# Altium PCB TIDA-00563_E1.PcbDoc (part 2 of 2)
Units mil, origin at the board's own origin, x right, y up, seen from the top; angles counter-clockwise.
Board outline 2300 x 2550 mil, 4 copper layers (Top Layer, MidLayer1 (GND), MidLayer2 (PWR), Bottom Layer), stack 79.8 mil thick; 81 components, 52 nets, 279 pads, 126 vias.
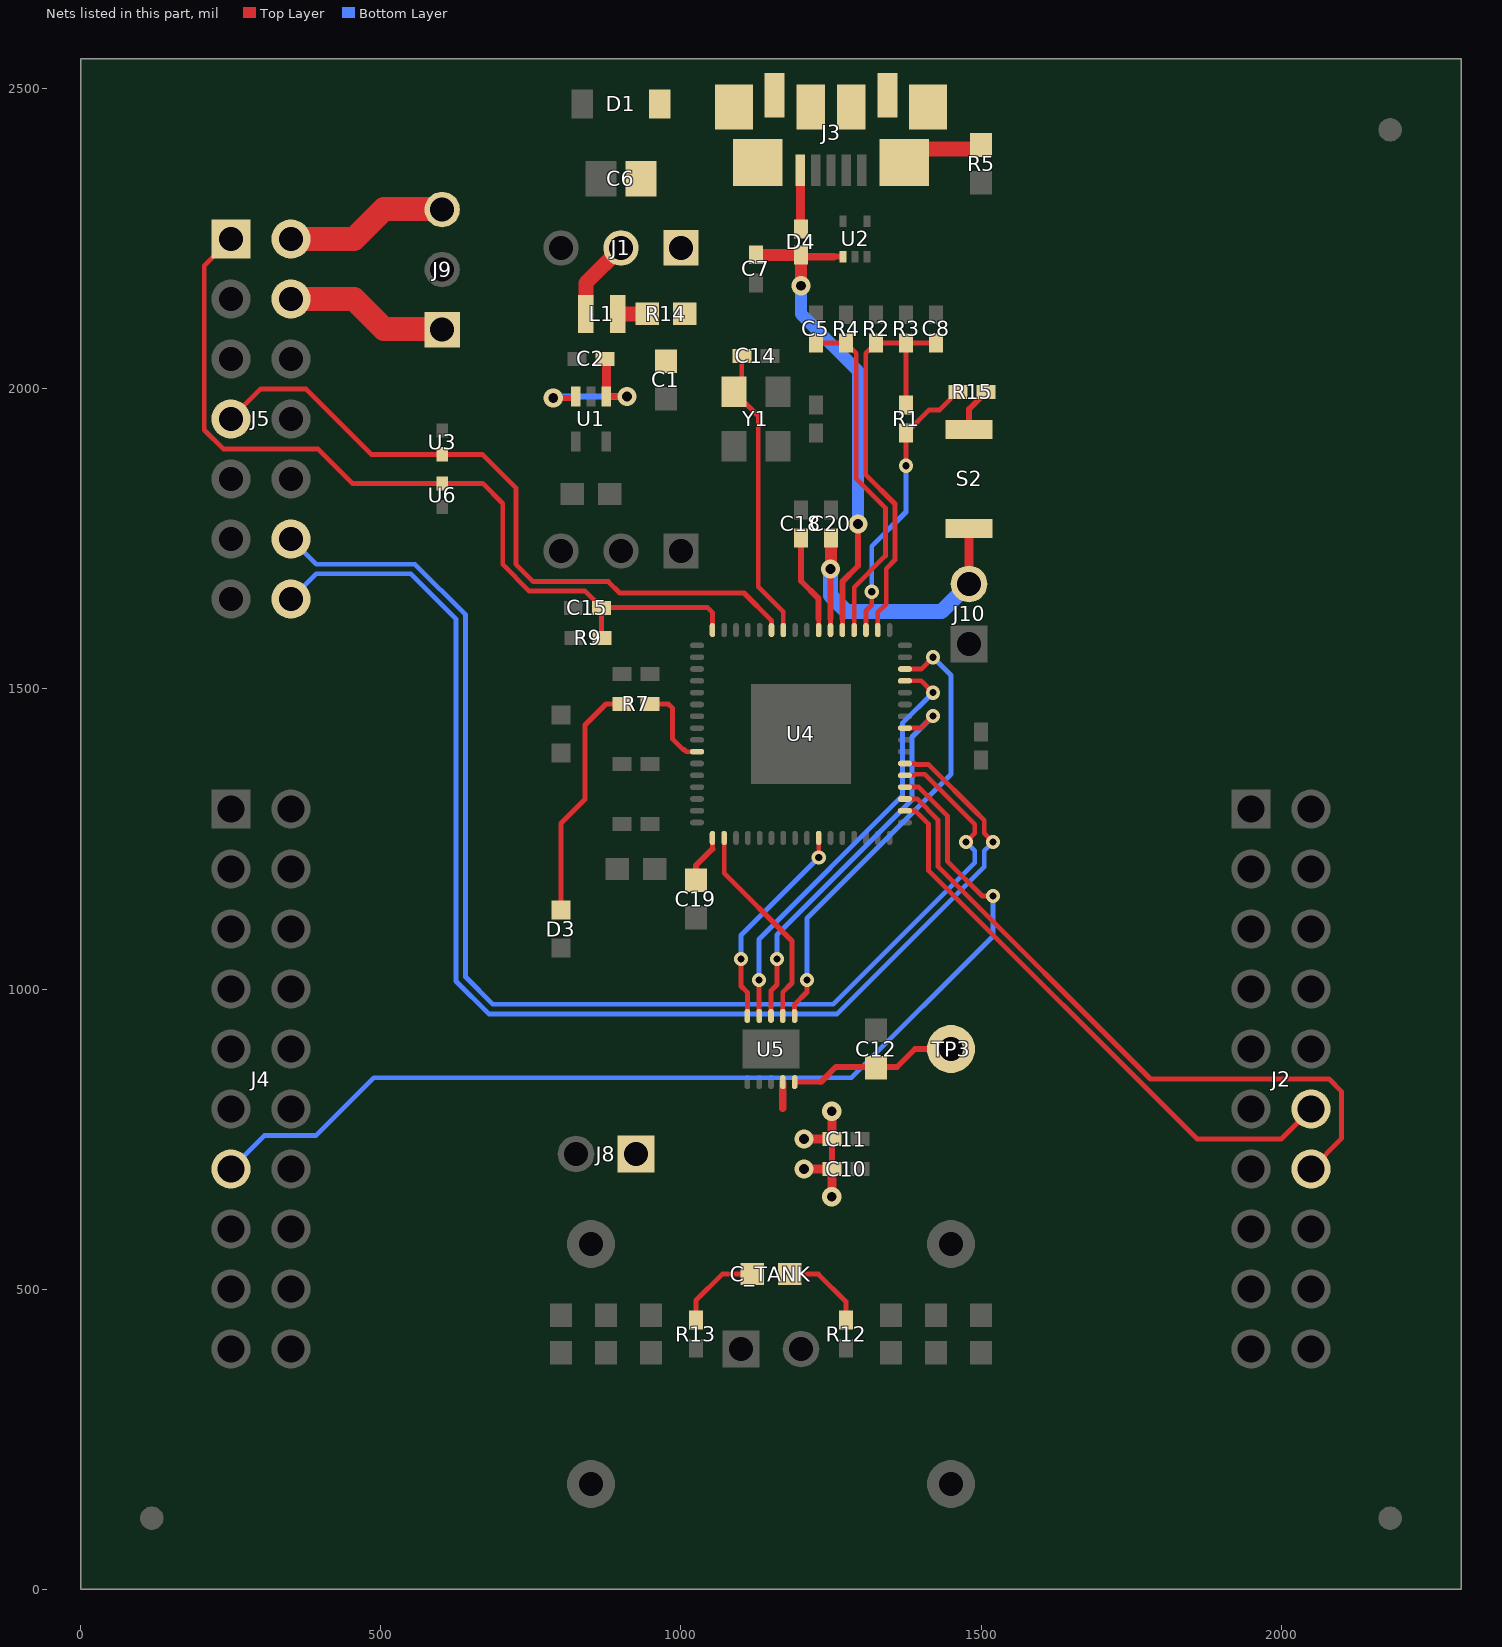
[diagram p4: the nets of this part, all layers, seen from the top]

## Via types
v1: diameter 32, hole 16, Top Layer to Bottom Layer, tented both sides, 96 vias
v2: diameter 19.68, hole 7.87, Top Layer to Bottom Layer, 17 vias
v3: diameter 24, hole 12, Top Layer to Bottom Layer, tented both sides, 13 vias

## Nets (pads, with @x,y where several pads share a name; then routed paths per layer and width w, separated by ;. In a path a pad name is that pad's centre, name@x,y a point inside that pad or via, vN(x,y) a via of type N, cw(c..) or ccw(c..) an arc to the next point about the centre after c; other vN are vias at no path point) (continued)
LDO_IN: C1.1 C2.1 R14.2 U1.1 U1.3 | length 258.5
  Top Layer w10: v1(787,1985) 822.01,1985 U1.3@824.41,1987.4 ; U1.1@875.59,1985 877.99,1987.4 v1(910.04,1987.4)
  Top Layer w15: U1.1@875.59,1987.4 C2.1@875.59,2048.03
  Bottom Layer w10: v1(787,1985) 789.4,1987.4 v1(910.04,1987.4)
MCU_CLKIN: U4.18 U5.2 | length 349.8
  Top Layer w8: U4.18@1072.02,1251.77 1072.02,1192.98 1185,1080 1185,1010 1169.69,994.69 U5.2@1169.69,955.11
MCU_CSB: U4.26 U5.5 | length 354.7
  Top Layer w8: v3(1100,1050) 1100,1005 1110.63,994.37 U5.5@1110.63,955.11 ; v3(1229.54,1219.2) U4.26@1229.54,1251.77
  Bottom Layer w8: v3(1100,1050) 1100,1089.66 v3(1229.54,1219.2)
MCU_SCLK: U4.41 U5.3 | length 666.8
  Top Layer w8: U5.3@1150,955.11 1150,997.45 1160,1007.45 v3(1160,1050) ; U4.41@1373.23,1434.84 1399.84,1434.84 v3(1420,1455)
  Bottom Layer w8: v3(1160,1050) 1160,1090.45 1385,1315.45 1385,1420 v3(1420,1455)
MCU_SDI: U4.45 U5.4 | length 714.1
  Top Layer w8: v3(1130,1015) 1130,955.43 U5.4@1130.32,955.11 ; U4.45@1373.23,1513.58 1400.26,1513.58 v3@1420,1493.84
  Bottom Layer w8: v3(1130,1015) 1130,1082.9 1369.13,1322.02 1369.13,1443.13 v3(1420,1494)
MISO_BP: J2.14 U4.35 | length 1125.4
  Top Layer w8: U4.35@1373.23,1316.73 1393.37,1316.73 1428.13,1281.98 1428.13,1204.32 1782.45,850 2080,850 2101,829 2101,751 J2.14@2050,700
MOSI_BP: J2.12 U4.34 | length 969.6
  Top Layer w8: U4.34@1373.23,1297.04 1390.61,1297.04 1412.25,1275.4 1412.25,1197.75 1860,750 2000,750 J2.12@2050,800
MSP_DM: C5.1 R4.2 U4.52 | length 576.9
  Top Layer w8: C5.1@1225,2076.38 R4.2@1275,2076.37 1292,2059.37 1292,1850.37 1340.69,1801.69 1340.69,1721.69 1288.61,1669.61 U4.52@1288.61,1598.23
MSP_DP: C8.1 R1.1 R2.2 R3.2 U4.50 | length 721.2
  Top Layer w8: U4.50@1327.99,1598.23 1327.99,1627.54 1342,1641.55 1342,1700.37 1356.69,1715.06 1356.69,1808.31 1308,1857 1308,2059.37 R2.2@1325,2076.37 R3.2@1375,2076.37 ; R1.1@1375,1973.62 R3.2@1375,2076.37 ; R3.2@1375.87,2075.5 R3.2@1375,2076.37 ; C8.1@1425,2076.38 R3.2@1375,2076.37
MSP_PUR: R1.2 R15.1 U4.51 | length 470.6
  Top Layer w8: U4.51@1308.3,1598.23 1308.3,1630.3 1318,1640 v3(1318,1662) ; v3(1375,1872) R1.2@1375,1926.38 1413.62,1965 1431.38,1965 R15.1@1461.38,1995
  Bottom Layer w8: v3(1318,1662) 1318,1738 1375,1795 v3(1375,1872)
MSP_XT2: C14.1 U4.58 Y1.3 | length 496
  Top Layer w8: C14.1@1101.38,2055 1101.38,2008.07 Y1.3@1088.59,1995.27 1128.88,1954.98 1128.88,1670.67 1170.47,1629.08 U4.58@1170.47,1598.23
MSPV18: C18.1 U4.55 | length 165.4
  Top Layer w8: U4.55@1229.54,1598.23 1229.54,1617
  Top Layer w10: C18.1@1200,1751.38 1200,1680 1229.54,1650.46 1229.54,1617
MSPVCORE: C19.1 U4.17 | length 81.6
  Top Layer w8: 1052.33,1233.33 U4.17@1052.33,1251.77
  Top Layer w10: C19.1@1025,1181.49 1025,1206 1052.33,1233.33
NetC10_1: C10.1 C11.1 J8.1 U5.9 | length 279.1
  Top Layer w10: C10.1@1251.38,700 C11.1@1251.38,750
  Top Layer w12: 1169.69,801.31 U5.9@1169.69,844.88
  Top Layer w15: v1(1205,700) C10.1@1251.38,700 v1(1251.38,653.62) ; v1(1205,750) C11.1@1251.38,750 v1(1251.38,796.38)
NetC12_1: C12.1 TP3.1 U5.10 | length 285.6
  Top Layer w8: U5.10@1189.37,844.88 1232.88,844.88 ; C12.1@1323.51,870 C12.1@1325,868.5
  Top Layer w10: 1232.88,844.88 1258,870 1323.51,870 1360,870 1390,900 TP3.1@1450,900
NetC_TANK_1: C_TANK.1 R12.1 | length 142.9
  Top Layer w8: C_TANK.1@1181.5,525 1229,525 1275,479 R12.1@1275,448.62
NetC_TANK_2: C_TANK.2 R13.2 | length 144.1
  Top Layer w8: R13.2@1025,448.62 1025,481 1069,525 C_TANK.2@1118.5,525
NetD4_2: D4.2 J3.1 | length 91.7
  Top Layer w15: D4.2@1198.82,2272.83 J3.1@1198.82,2364.49
NetJ1_2: J1.2 L1.1 | length 134.3
  Top Layer w25: L1.1@841.43,2125 841.43,2176.43 J1.2@900,2235
NetL1_2: L1.2 R14.1 | length 48.9
  Top Layer w25: L1.2@894.57,2125 R14.1@943.5,2125
NetR15_2: R15.2 S2.1 | length 74.2
  Top Layer w10: S2.1@1480,1932.68 1480,1966.38 R15.2@1508.62,1995
RLED: R7.1 U4.10 | length 141.3
  Top Layer w8: R7.1@948.63,1475 979.13,1475 986,1468.13 986,1416.55 1003.27,1399.28 1005.28,1399.28 1009.09,1395.47 U4.10@1026.78,1395.47
RLEDA: D3.2 R7.2 | length 401
  Top Layer w8: D3.2@800,1131.5 800,1276 840,1316 840,1440 875,1475 R7.2@901.38,1475
SBWTCK: J5.7 U3.1 U4.59 | length 1184.7
  Top Layer w8: J5.7@250,1950 300,2000 374.86,2000 483.86,1891 669,1891 ; 656,1891 669,1891 ; U4.59@1150.78,1598.23 1150.78,1614.22 1105,1660 898,1660 879,1679 754,1679 725,1708 725,1835 669,1891
SBWTDIO: C15.1 J5.1 R9.2 U4.64 U6.1 | length 1449.6
  Top Layer w8: J5.1@250,2250 205.65,2205.65 205.65,1931.63 237.27,1900 395,1900 452.32,1842.68 U6.1@602,1842.68 669.32,1842.68 702.87,1809.13 702.87,1707.68 747.42,1663.13 840.5,1663.13 C15.1@867.62,1636 ; R9.2@868.63,1585 867.62,1586 C15.1@867.62,1635 C15.1@867.62,1636 ; U4.64@1052.33,1598.23 1052.33,1627.67 1044,1636 C15.1@867.62,1636
SCLK_BP: J4.13 U4.36 | length 1763.9
  Top Layer w8: U4.36@1373.23,1336.41 1396.14,1336.41 1444,1288.55 1444,1213 1502,1155 v3(1520,1155)
  Bottom Layer w8: J4.13@250,700 305.65,755.65 391.65,755.65 488,852 1284,852 1520,1088 v3(1520,1155)
SDO: U4.46 U5.1 | length 773.2
  Top Layer w8: U5.1@1189.37,955.11 1189.37,974.37 1210,995 v3(1210,1015) ; U4.46@1373.23,1533.26 1400.26,1533.26 v3(1420,1553)
  Bottom Layer w8: v3(1210,1015) 1210,1118 1450,1358 1450,1523 v3(1420,1553)
UART_RXD: J5.14 U4.38 | length 2192.7
  Top Layer w8: U4.38@1373.23,1375.78 1389.04,1375.78 1390.89,1373.94 1412.69,1373.94 1495.81,1290.81 ; 1496,1290.63 1505.5,1281.13 1505.5,1259.5 v3(1520,1245)
  Bottom Layer w8: J5.14@350,1650 392,1692 550,1692 625,1617 625,1013.37 679.87,958.5 1260.5,958.5 1505.5,1203.5 1505.5,1230.5 v3(1520,1245)
UART_TXD: J5.12 U4.37 | length 2139.9
  Top Layer w8: U4.37@1373.23,1356.1 1389.04,1356.1 1390.89,1357.94 1406.06,1357.94 1489.5,1274.5 1489.5,1259.5 v3(1475,1245)
  Bottom Layer w8: J5.12@350,1750 392,1708 556.63,1708 641,1623.63 641,1020 686.5,974.5 1253.87,974.5 1489.5,1210.13 1489.5,1230.5 v3(1475,1245)
UGND: J3.6 J3.7 J3.8 J3.9 J3.10 J3.11 J3.12 J3.13 R5.2 | length 140
  Top Layer w20: J3.6@1372.05,2377.48 J3.6@1394.57,2400
  Top Layer w25: J3.6@1394.57,2400 1493.5,2400 R5.2@1500,2406.5
VBUS: C6.1 C7.1 D1.1 D4.1 J1.1 U2.1 U4.53 | length 821.9
  Top Layer w8: U4.53@1268.92,1598.23 1268.92,1616 1268.92,1617
  Top Layer w10: D4.1@1200,2223.35 D4.1@1202.87,2220.47 ; 1255,2220.47 U2.1@1270.31,2220.47 ; 1268.92,1617 1268.92,1678.86 1295,1704.94 v1(1295,1775)
  Top Layer w12: D4.1@1202.87,2220.47 1255,2220.47
  Top Layer w15: C7.1@1125,2223.62 C7.1@1125.28,2223.35
  Top Layer w20: C7.1@1125.28,2223.35 D4.1@1200,2223.35 v1(1200,2171.97)
  Bottom Layer w20: v1(1200,2171.97) 1200,2125 1295,2030 v1(1295,1775)
VCC_TARGET: J5.4 J9.1 | length 287.7
  Top Layer w10: J9.1@602,2083 J9.1@602,2099
  Top Layer w40: J5.4@350,2150 455,2150 505,2100 J9.1@601,2100
VCC_TOOL: J5.2 J9.3 | length 289.1
  Top Layer w10: J9.3@586,2283 J9.3@602,2283
  Top Layer w40: J5.2@350,2250 455,2250 505,2300 601,2300 J9.3@602,2299
VUSB: C20.1 J10.2 S2.2 U4.54 | length 550.9
  Top Layer w8: U4.54@1249.23,1598.23 1249.23,1617
  Top Layer w10: 1249.23,1617 v1(1249.23,1700)
  Top Layer w15: J10.2@1480,1675 S2.2@1480,1767.32
  Top Layer w20: v1(1249.23,1700) 1250,1700.77 C20.1@1250,1751.38
  Bottom Layer w25: v1(1249.23,1700) 1249.23,1655.77 1276,1629 1434,1629 J10.2@1480,1675
pads on no net: FID1.1 FID2.1 FID3.1 J2.1 J2.3 J2.4 J2.5 J2.6 J2.7 J2.8 J2.9 J2.10 J2.11 J2.13 J2.16 J2.20 J3.4 J4.3 J4.5 J4.6 J4.7 J4.8 J4.9 J4.10 J4.11 J4.12 J4.14 J4.15 J4.16 J4.17 J4.18 J4.19 J4.20 J5.3 J5.5 J5.6 J5.8 J5.10 J5.11 J5.13 SH-J1.0 SH-J7.0 SH-J8.0 SH-J9.0 SH-J10.0 U1.4 U4.1 U4.2 U4.3 U4.4 U4.5 U4.6 U4.7 U4.8 U4.12 U4.13 U4.19 U4.20 U4.21 U4.22 U4.23 U4.24 U4.25 U4.27 U4.28 U4.29 U4.42 U4.43 U4.44 U4.47 U4.48 U4.60 U4.61 U4.62 U4.63

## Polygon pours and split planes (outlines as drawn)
+3.3V on Top Layer "Bottom Layer-No Net" (solid, remove dead copper, pour order 21): 932,1442 932,1128 977,1128 977,1388 967,1388 967,1442
NetC10_1 on Top Layer "Top Layer-No Net 6" (solid, remove dead copper, pour order 20): 1164,814 1164,636 1268,636 1268,814
NetL1_2 on Top Layer "Top Layer-No Net 5" (solid, remove dead copper, pour order 19): 881,2157 881,2093 964,2093 964,2157 881,2157
+3.3V_LDO on Top Layer "Top Layer-+3.3V_LDO" (solid, remove dead copper, pour order 18): 860,1930 860,1806 970,1806 970,1700 1060,1700 1060,1850 1040,1850 1040,1930
VBUS on Top Layer "Top Layer-No Net 2" (solid, remove dead copper, pour order 17): 945,2505 945,2385 905,2385 905,2315 970,2315 970,2205 1150,2205 1150,2300 1020,2300 1020,2505
UGND on Top Layer "Top Layer-No Net 1" (solid, remove dead copper, pour order 15): 1055,2530 1055,2335 1170,2335 1170,2430 1330,2430 1330,2335 1445,2335 1445,2530
GND on Top Layer "Top Layer-No Net" (solid, remove dead copper, pour order 16): 1065,1560 1065,1290 1335,1290 1335,1560 1065,1560
LDO_IN on Top Layer "Top Layer-LDO_IN" (solid, remove dead copper, pour order 28): 986,2160 986,2070 982,2066 862,2066 861,2066 857,2062 856,2061 856,2037 856,2036 857,2035 866,2026 995,2026 1027,2026 1030,2029 1030,2111 1030,2160 986,2160
GND on Top Layer "Top Layer-GND" (solid, remove dead copper, pour order 27): 22.63,2527.37 22.63,2367.37 22.63,7.37 32.63,-2.63 152.63,-2.63 2292.63,-2.63 2302.63,7.37 2302.63,2517.37 2292.63,2527.37 22.63,2527.37
NetC10_1 on Bottom Layer "Bottom Layer-No Net 1" (solid, remove dead copper, pour order 23): 1268,814 894,814 894,636 1268,636 1268,814
GND on Bottom Layer "Bottom Layer-GND" (solid, remove dead copper, pour order 26): 22.63,2527.37 22.63,2367.37 22.63,7.37 32.63,-2.63 152.63,-2.63 2292.63,-2.63 2302.63,7.37 2302.63,2517.37 2292.63,2527.37 22.63,2527.37
+3.3V on MidLayer2 (PWR) "PWR-+3.3V" (solid, remove dead copper, pour order 25): 10,2540 10,2380 10,20 20,10 140,10 2280,10 2290,20 2290,2530 2280,2540 10,2540
GND on MidLayer1 (GND) "GND-GND" (solid, remove dead copper, pour order 24): 10,2540 10,2380 10,20 20,10 140,10 2280,10 2290,20 2290,2530 2280,2540 10,2540

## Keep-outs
Keep-Out Layer:
  the board outline again, w11.81
  text ".Layer_Name" at 764,-871 h60

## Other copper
Top Layer:
  text ".Layer_Name" at 736,-853 h60
MidLayer1 (GND):
  text ".Layer_Name" at 736,-853 h60
MidLayer2 (PWR):
  text ".Layer_Name" at 719,-860 h60
Bottom Layer:
  text ".Layer_Name" at 778,-860 h60

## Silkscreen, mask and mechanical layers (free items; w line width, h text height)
Top Overlay:
  circle w10: c1270,2199 r1
  circle w10: c635,1842.68 r1
  circle w10: c635,1891 r1
  circle w10: c1191,983 r1
  circle w10: c1424.63,1943.17 r1
  circle w10: c1159,1855 r1
  region: 1998,2497 1998,2197 2098,2197 2098,2497
  lines w6: 750,795 1550,795 ; 750,1005 1550,1005 ; 999,1571 986,1584 986,1556 1000,1570 ; 1082,468 1100,450 1119,469 1082,469
  lines w7: 398.42,1200 493.94,1200 493.94,1160 ; 433.94,1160 553.94,1160 ; 453.94,1140 533.94,1140 ; 473.94,1120 513.94,1120 ; 790.5,74 910.5,74 ; 810.5,54 890.5,54 ; 830.5,34 870.5,34 ; 850.5,74 850.5,114 ; 1390.5,74 1510.5,74 ; 1410.5,54 1490.5,54 ; 1430.5,34 1470.5,34 ; 1450.5,74 1450.5,114 ; 2098.42,1300 2193.94,1300 2193.94,1260 ; 2133.94,1260 2253.94,1260 ; 2153.94,1240 2233.94,1240 ; 2173.94,1220 2213.94,1220
  lines w10: 750,0 1550,0 1550,2550 750,2550 750,0
  text "-" at 2073,2123 h25 r90
  text ".PCB_Rev" at 2070,2017 h40 r90
  text ".TID" at 2070,1570 h40 r90
  text "BP1" at 205,1385 h25
  text "BP21" at 315,1385 h25
  text "BP40" at 1895,1385 h25
  text "BP20" at 2020,1385 h25
  text "LDC1101" at 775,940 h70
  text "BP10" at 200,290 h25
  text "BP30" at 320,290 h25
  text "BP31" at 1900,290 h25
  text "BP11" at 2015,290 h25
  text ".Layer_Name" at 659,-864 h60
Bottom Overlay:
  lines w6: 166,1319 166,1282 185,1301 167,1319 ; 1867,1316 1867,1279 1886,1298 1868,1316
  text ".Layer_Name" at 666,-853 h60
Top Paste:
  text ".Layer_Name" at 827,-853 h60
Bottom Paste:
  text ".Layer_Name" at 925,-850 h60
Top Solder:
  text ".Layer_Name" at 820,-860 h60
Bottom Solder:
  text ".Layer_Name" at 1016,-864 h60
Drill Guide:
  text ".Layer_Name" at 967,-853 h60
M1 Board Outline:
  the board outline again, w11.81
M2 Board Dimensions:
  rectangle: 0,-275 125,-150
  rectangle: 125,-400 500,-275
  lines w7: 0,-275 1000,-275 ; 125,-400 125,-150 ; 250,-400 250,-150 ; 500,-400 500,-150 ; 750,-400 750,-150 ; 0,-400 1000,-400 1000,-150 0,-150 0,-400
M3 3D STEP Top:
  text ".Layer_Name" at 806,-864 h60
M4 3D STEP Bottom:
  text ".Layer_Name" at 743,-867 h60
M5 Assembly Top:
  circle w4: c636,1891 r5.66
  circle w4: c636,1842.68 r5.66
  circle w4: c1438,1940 r5.66
  circle w4: c1271,2203 r5.66
  circle w4: c879,1995 r5.66
  circle w4: c1006,1561 r5.66
  circle w4: c1418,1574 r5.66
  circle w4: c929,788 r5.66
  circle w4: c1100,320 r5.66
  lines w10: -292,-930.17 6308,-930.17 ; -292,-726.83 6310,-726.83 ; -292,-523.5 -292,-1133.5 3713,-1133.5 6310,-1133.5 6310,-523.5 -291.5,-523.5 -291.5,-1133.5 1284,-1133.5 ; 2173,-1133.5 2173,-523.5 ; 3440,-726.83 3440,-523.5 ; 4280,-726.83 4280,-523.5 ; 4902,-1140 4902,-937.17
  text "COMPONENTS MARKED 'DNP' SHOULD NOT BE POPULATED." at 1153.5,-318.5 h60
  text "ASSEMBLY VARIANT:" at 1153,-434 h60
  text ".VariantName" at 2189,-434 h60
  text "SVN REV:" at 4410,-655 h60
  text "PCB VIEWED FROM TOP SIDE" at -228.5,-655.67 h60
  text "BOARD #:" at 2248,-655.67 h60
  text ".PRJ_Number" at 2793.5,-655.67 h60
  text "REV:" at 3638,-655.67 h60
  text ".PCB_Rev" at 3929.5,-655.67 h60
  text ".VersionControl_RevNumber" at 4890,-660 h60
  text ".Layer_Name" at 638,-857 h60
  text "LAYER NAME =" at -231,-863 h60
  text "PLOT NAME=" at -228.5,-1064.34 h60
  text "TEXAS INSTRUMENTS" at 5113,-1064.34 h60
  text ".plot_File_Name" at 376,-1068 h60
  text "GENERATED    :" at 2714.5,-1068 h60
  text ".Print_Date" at 3584,-1068 h60
  text ".Print_Time" at 4313,-1068 h60
M6 Assembly Bottom:
  circle w4: c1883,1301 r5.66
  circle w4: c181,1298 r5.66
  lines w10: -292.5,-727.33 6309.5,-727.33 ; -290.5,-930.67 6309.5,-930.67 ; 1115.5,-1140.5 1115.5,-937.67 ; 1737.5,-727.33 1737.5,-524 ; 2577.5,-727.33 2577.5,-524 ; 3844.5,-1134 3844.5,-524 ; 4733.5,-1134 6309,-1134 6309,-524 -292.5,-524 -292.5,-1134 2304.5,-1134 6309.5,-1134 6309.5,-524
  text "COMPONENTS MARKED 'DNP' SHOULD NOT BE POPULATED." at 6102,-318 h60
  text ".VariantName" at 5058,-434 h60
  text "ASSEMBLY VARIANT:" at 6097,-434 h60
  text ".VersionControl_RevNumber" at 1035.5,-656.17 h60
  text "SVN REV:" at 1541.5,-656.17 h60
  text ".PCB_Rev" at 2088,-656.17 h60
  text "REV:" at 2379.5,-656.17 h60
  text ".PRJ_Number" at 3224,-656.17 h60
  text "BOARD #:" at 3769.5,-656.17 h60
  text "PCB VIEWED FROM BOTTOM SIDE" at 6246,-656.17 h60
  text ".Layer_Name" at 1721,-864 h60
  text "LAYER NAME =" at 2507,-868 h60
  text "TEXAS INSTRUMENTS" at 904.5,-1064.84 h60
  text "PLOT NAME =" at 6246,-1064.84 h60
  text ".Print_Time" at 1752,-1066 h60
  text ".Print_Date" at 2481,-1066 h60
  text "GENERATED    :" at 3350.5,-1066 h60
  text ".plot_File_Name" at 5589,-1068 h60
M9 Title Sheet:
  drawing of 56 lines, arcs and shapes, not listed
  text "1" at 739.84,8036.5 h45
  text "2" at 3235.5,8036.5 h45
  text "3" at 5724.84,8036.5 h45
  text "4" at 8231.51,8036.5 h45
  text "5" at 10730.5,8036.5 h45
  text "6" at 13235.5,8036.5 h45
  text "A" at -416.5,6893.5 h45
  text "A" at 14383.5,6893.5 h45
  text "B" at -416.5,4513.5 h45
  text "B" at 14383.5,4513.5 h45
  text "C" at -416.5,2138.5 h45
  text "C" at 14383.5,2138.5 h45
  text "PROJECT TITLE:" at 11343.5,277.5 h45
  text ".PRJ_Title" at 11393.5,144.17 h45
  text "DESIGNED FOR:" at 11343.5,-23.5 h45
  text ".PRJ_Customer" at 11393.5,-163.5 h45
  text "D" at -416.5,-231.5 h45
  text "D" at 14383.5,-231.5 h45
  text "FILE NAME:" at 11343.5,-323.5 h45
  text ".PCB_File_Name_No_Path" at 11393.5,-443.5 h45
  text "Texas Instruments (TI) and/or its licensors do not warrant the accuracy or completeness of this specification" at 6374,-605.34 h45
  text "ENGINEER:" at 11343.5,-613.5 h45
  text "LAYOUT BY:" at 12848.5,-613.5 h45
  text "or any information contained therein. TI and/or its licensors do not warrant that this design will meet" at 6329.01,-718 h45
  text ".PRJ_Engineer" at 11393.5,-768.49 h45
  text ".PCB_Layout" at 12899,-768.49 h45
  text "the specifications, will be suitable for your application or fit for any particular purpose, or will operate in" at 6329.01,-830.67 h45
  text "ALTIUM DESIGNER VERSION:" at 12848.5,-923.5 h45
  text "an implementation. TI and/or its licensors do not warrant that the design is production worthy. You should" at 6329.01,-943.33 h45
  text "completely validate and test your design implementation to confirm the system functionality for your application." at 6374,-1056 h45
  text ".print_Scale" at 11393.5,-1056.83 h45
  text ".Application_BuildNumber" at 12899,-1056.83 h45
  text "1" at 739.84,-1263.5 h45
  text "2" at 3235.5,-1263.5 h45
  text "3" at 5724.84,-1263.5 h45
  text "4" at 8231.51,-1263.5 h45
  text "5" at 10730.5,-1263.5 h45
  text "6" at 13235.5,-1263.5 h45
M10 Fab Notes:
  drawing of 228 lines, arcs and shapes, not listed
  text "DESIGN INFORMATION" at 12301.13,6274 h60
  text "(REFER ALSO ARRAY/PANEL PROFILING INFORMATION)" at 12053.59,6134.29 h60
  text "BOARD SIZE" at 11367.59,6130 h60
  text "2550.00MIL" at 12495,6005 h60
  text "X" at 12335.59,6002.18 h60
  text "2300.00MIL" at 11770,6000 h60
  text "4" at 12836.13,5884 h60
  text "Number of Layers :" at 11736.13,5868 h60
  text "MIN. TRACK WIDTH:" at 11736.96,5754.37 h60
  text "8" at 12833.2,5754.37 h60
  text "MIL" at 12987.96,5754.37 h60
  text "MIN. CLEARANCE:" at 11736.96,5622.37 h60
  text "7.865" at 12719,5619 h60
  text "MIL" at 13004,5618 h60
  text "MIN. VIA PAD SIZE:" at 11736.96,5490.37 h60
  text "19.685" at 12644,5490 h60
  text "MIL" at 12987.96,5490.37 h60
  text "0.149mm (5.905MIL)" at 12431.96,5348.66 h60
  text "MINIMUM ANNULAR RING" at 11407.73,5344.37 h60
  text "EXTERNAL" at 13295,5343 h60
  text "PER" at 11607.73,5226.37 h60
  text "IPC-D-275 CLASS 2 LEVEL C" at 11827.73,5226.37 h60
  text "MIL, HOLES" at 13315.96,5114.08 h60
  text "+/-" at 12923.5,5113.37 h60
  text "+/-" at 13777.5,5113.37 h60
  text "REGISTRATION TOLERANCES:" at 11407.73,5108.37 h60
  text "METAL" at 12607.5,5108.37 h60
  text "5" at 13183.7,5108.37 h60
  text "3" at 14016.7,5108.37 h60
  text "MIL" at 14132.96,5108.37 h60
  text "MATERIAL:" at 11332.96,4963.91 h60
  text "FR-4 High Tg" at 12319.4,4823.58 h60
  text "FR-408" at 11753.96,4815.01 h60
  text "OTHER" at 13241.96,4815.01 h60
  text "X" at 12162.13,4808 h60
  text "63 MIL (1.6mm) +/-10%" at 12074.06,4652.29 h60
  text "THICKNESS:" at 11407.73,4648.01 h60
  text "X" at 11945.9,4648.01 h60
  text "OTHER" at 13358.96,4648.01 h60
  text "TOLERANCE:" at 11407.73,4490.01 h60
  text "X" at 12247.03,4490.01 h60
  text "ANSI IPC-6012 TYPE 3 CLASS 2" at 12433.98,4490.01 h60
  text "OTHER +/-" at 12433.96,4334.01 h60
  text "BOW & TWIST:" at 11407.73,4177.01 h60
  text "X" at 12247.03,4177.01 h60
  text "ANSI IPC-6012 TYPE 3 CLASS 2" at 12433.98,4177.01 h60
  text "OTHER +/-" at 12433.96,4018.5 h60
  text "COPPER THICKNESS (FINISHED):" at 11330,3900 h60
  text "1.4MIL (1oz)" at 12148.46,3798.92 h60
  text "2MIL (1.4oz)" at 12915.46,3798.92 h60
  text "2.8MIL (2oz)" at 13642.46,3798.92 h60
  text "OUTER:" at 11625.46,3794.64 h60
  text "X" at 12020,3794 h60
  text "1.4MIL (1oz)" at 12153.46,3641.92 h60
  text "2.8MIL (2oz)" at 12920.46,3641.92 h60
  text "N/A" at 13647,3642.29 h60
  text "INNER SIGNAL:" at 11341.38,3637.64 h60
  text "X" at 12025,3637 h60
  text "DRILLING:" at 11345,3515 h60
  text "X" at 12075.96,3438.01 h60
  text "AS SHOWN" at 12262.96,3438.01 h60
  text "X" at 12976.96,3438.01 h60
  text "NC_DRILL FILES" at 13113.96,3438.01 h60
  text "REFERENCE:" at 11520,3420 h60
  text "PTH MIN COPPER THICKNESS:" at 11427.73,3280.01 h60
  text "X" at 12777.96,3280.01 h60
  text "1MIL" at 12914.96,3280.01 h60
  text "OTHER" at 13411.96,3280.01 h60
  text "BOARD FINISH:" at 11332.96,3196.01 h60
  text "X" at 12946.96,3083.01 h60
  text "SILKSCREEN:" at 11488.18,3078.01 h60
  text "X" at 12436.96,3078.01 h60
  text "TOP" at 12562.96,3078.01 h60
  text "BOTTOM" at 13073.96,3078.01 h60
  text "SILKSCREEN COLOR:" at 11488.18,2911.01 h60
  text "X" at 12435.92,2911.01 h60
  text "WHITE" at 12562.96,2911.01 h60
  text "OTHER" at 13073.96,2911.01 h60
  text "SOLDER RESIST COLOR:" at 11488.18,2741.01 h60
  text "X" at 12055.92,2581.81 h60
  text "GREEN" at 12182.96,2581.81 h60
  text "BLUE" at 12773.96,2581.81 h60
  text "OTHER" at 13311.96,2581.81 h60
  text "IMMERSION GOLD (ENIG)" at 12423.96,2433.29 h60
  text "ENEPIG" at 13761.5,2430.01 h60
  text "SURFACE FINISH:" at 11362.96,2429.01 h60
  text "X" at 12237.01,2429.01 h60
  text "IMM. TIN/SILVER OR EQUIV" at 11692.5,2272.01 h60
  text "OTHER" at 13123.96,2272.01 h60
  text "ARRAY/PANEL:" at 11357.96,2138.01 h60
  text "CUT AND TRIM PER MECH LAYER 1" at 12418.96,2133.72 h60
  text "N.C. ROUTE" at 12418.96,1982.01 h60
  text "X" at 13097.96,1982.01 h60
  text "V. SCORE" at 13284.96,1982.01 h60
  text "CERTIFICATION:" at 11357.96,1845.01 h60
  text "MATERIALS AND WORKMANSHIP FOR ALL PCBS" at 12082.96,1845.01 h60
  text "TO MEET OR EXCEED THE REQUIREMENTS OF:" at 12082.96,1747.01 h60
  text "X" at 11709.46,1610.51 h60
  text "ANSI IPC-A-600F CLASS ->" at 11848.46,1610.51 h60
  text "X" at 13487.52,1610.51 h60
  text "2" at 13606.46,1610.51 h60
  text "1" at 13291.46,1609.01 h60
  text "3" at 13960.46,1609.01 h60
  text "X" at 11711.52,1451.01 h60
  text "UL 94V-0" at 11848.46,1451.01 h60
  text "X" at 12523.52,1451.01 h60
  text "RoHS" at 12660.46,1451.01 h60
  text "OTHER" at 13304.86,1451.01 h60
  text "PER ORDER" at 13701.92,1451.01 h60
  text "ADDITIONAL REQUIREMENTS:" at 11357.96,1310.01 h60
  text "NO" at 13694.58,1298.54 h60
  text "VIA TENTING" at 12609.13,1289 h60
  text "X" at 13178.85,1286.83 h60
  text "YES" at 13293.11,1283.44 h60
  text "IMPEDANCE CONTROL:" at 12567.13,1159 h60
  text "MICROSECTION:" at 11444.73,1158.01 h60
  text "YES" at 12350.46,1158.01 h60
  text "YES" at 13535.13,1158 h60
  text "X" at 14093.13,1151 h60
  text "NO" at 13926.6,1140.69 h60
  text "REQUIRED" at 13199.96,987.86 h60
  text "BARE BOARD ELEC. TEST:" at 11432.73,985.01 h60
  text "NONE" at 12738.46,985.01 h60
  text "X" at 13072.96,985.01 h60
  text "PER ORDER" at 13791.96,985.01 h60
  text "MANUFACTURER'S UL:" at 11432.73,828.01 h60
  text "RAIL" at 12598.46,823.72 h60
  text "METAL" at 13090.27,823.72 h60
  text "SILK" at 13601.96,823.72 h60
  text "X" at 13465.5,823.37 h60
M11 Gerber Information:
  lines w10: -292,-930.17 6308,-930.17 ; -292,-726.83 6310,-726.83 ; -292,-523.5 -292,-1133.5 3713,-1133.5 6310,-1133.5 6310,-523.5 -291.5,-523.5 -291.5,-1133.5 1284,-1133.5 ; 2463,-1133.5 2463,-523.5 ; 3585,-726.83 3585,-523.5 ; 4280,-726.83 4280,-523.5 ; 4902,-1140 4902,-937.17
  text "BOARD #:" at 2495,-655 h60
  text "ALL ARTWORK VIEWED FROM TOP SIDE" at -228.5,-655.67 h60
  text "REV:" at 3638,-655.67 h60
  text ".PCB_Rev" at 3929.5,-655.67 h60
  text "SVN REV:" at 4476,-655.67 h60
  text ".VersionControl_RevNumber" at 4982,-655.67 h60
  text ".PRJ_Number" at 2980,-660 h60
  text "LAYER NAME=" at -228.5,-858.49 h60
  text ".plot_File_Name" at 385,-1060 h60
  text "GENERATED    :" at 2580.5,-1060 h60
  text ".Print_Date" at 3450,-1060 h60
  text ".Print_Time" at 4179,-1060 h60
  text "PLOT NAME=" at -228.5,-1064.34 h60
  text "TEXAS INSTRUMENTS" at 5113,-1064.34 h60
M12 Stackup:
  lines w8: 11406.13,7425.5 14076.13,7425.5 ; 11406.13,7577 14076.13,7577 ; 11346.13,6458 ccw(c11395.13,6458) 11395.13,6409 14087.13,6409 ccw(c14087.13,6458) 14136.13,6458 14136.13,7710 ccw(c14087.13,7710) 14087.13,7759 11395.13,7759 ccw(c11395.13,7710) 11346.13,7710 11346.13,6458
  text "The Stackup Legend below this is static." at 11540,7878 h45
  text "If you change the stackup, update the Legend." at 11484,7794 h45
  text "Layer Stack Up Detail for: BoosterPack_40pin_Template_EVM.PcbDoc" at 11410,7650 h40
  text "Layer" at 11406.13,7520.5 h45
  text "Gerber" at 12360.86,7520.5 h45
  text "Copper" at 12842.88,7520.5 h45
  text "Dielectric" at 13382.04,7520.5 h45
  text "Name" at 11406.13,7450.5 h45
  text "Document" at 12360.86,7450.5 h45
  text "Thickness" at 12842.88,7450.5 h45
  text "Material" at 13382.04,7450.5 h45
  text "Top Solder Mask" at 11406.13,7351.19 h45
  text "(.GTS)" at 12360.86,7351.19 h45
  text "Solder Resist" at 13382.04,7351.19 h45
  text "Top Layer" at 11406.13,7210.56 h45
  text "(.GTL)" at 12360.86,7210.56 h45
  text "1.4mil" at 12842.88,7210.56 h45
  text "FR-4 High Tg" at 13382.04,7140.25 h45
  text "MidLayer1 (GND)" at 11406.13,7069.94 h45
  text "(.G1)" at 12360.86,7069.94 h45
  text "1.4mil" at 12842.88,7069.94 h45
  text "FR-4 High Tg" at 13382.04,6999.62 h45
  text "MidLayer2 (PWR)" at 11406.13,6929.31 h45
  text "(.G2)" at 12360.86,6929.31 h45
  text "1.4mil" at 12842.88,6929.31 h45
  text "FR-4 High Tg" at 13382.04,6859 h45
  text "Bottom Layer" at 11406.13,6788.69 h45
  text "(.GBL)" at 12360.86,6788.69 h45
  text "1.4mil" at 12842.88,6788.69 h45
  text "Bottom Solder Mask" at 11406.13,6648.06 h45
  text "(.GBS)" at 12360.86,6648.06 h45
  text "Solder Resist" at 13382.04,6648.06 h45
M13 Component Bodies Top:
  text ".Layer_Name" at 659,-860 h60
M15 Courtyards Top:
  text ".Layer_Name" at 736,-853 h60
M16 Courtyards Bottom:
  text ".Layer_Name" at 645,-853 h60
Drill Drawing:
  text ".legend" at 3337,897 h60
  text "Drill Table" at 3347,727 h60
  text "DRILL TOLERANCE" at 3341.72,613.52 h60
  text "FOR PTH +/- 3MIL" at 3342.14,504.09 h60
  text "7.874mil drill:+0/-7.874mil" at 3336,390 h60
  text "12mil drill:+0/-12mil" at 3333,277 h60
  text "16mil drill:+0/-16mil" at 3335,169 h60
  text ".Layer_Name" at 858,-846 h60

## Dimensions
0,2550 to 2300,2550 on M2 Board Dimensions
0,2550 to 0,0 on M2 Board Dimensions
0,-400 to 1000,-400 on M2 Board Dimensions
750,0 to 1550,0 on Top Overlay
